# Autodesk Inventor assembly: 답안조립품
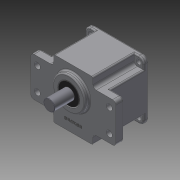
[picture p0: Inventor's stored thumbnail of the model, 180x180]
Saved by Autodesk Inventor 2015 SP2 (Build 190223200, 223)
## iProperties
Created: 2015-06
Part Number: 답안조립품
Document SubType Name: Assembly
Designer: AMC
Author: AMC
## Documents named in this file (12)
- C:\Users\AMC\Desktop\450620V1005\답안조립품.iam
- C:\Users\AMC\Desktop\450620V1005\본체.ipt
- C:\Users\AMC\Desktop\450620V1005\오일실 17x32x8.ipt
- C:\Users\AMC\Desktop\450620V1005\베어링 6003.ipt
- 베어링 6003.ipt
- C:\Users\AMC\Desktop\450620V1005\베어링 608.ipt
- 베어링 608.ipt
- C:\Users\AMC\Desktop\450620V1005\메인축.ipt
- C:\Users\AMC\Desktop\450620V1005\서브축.ipt
- C:\Users\AMC\Desktop\450620V1005\커버.ipt
- C:\Users\AMC\Desktop\450620V1005\오일실 8x22x7.ipt
- C:\Users\AMC\Desktop\450620V1005\M4x0.5x16.ipt
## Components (4 placed, 1 different names)
1. M4x0.5x12:1
2. M4x0.5x12:2
3. M4x0.5x12:3
4. M4x0.5x12:4
